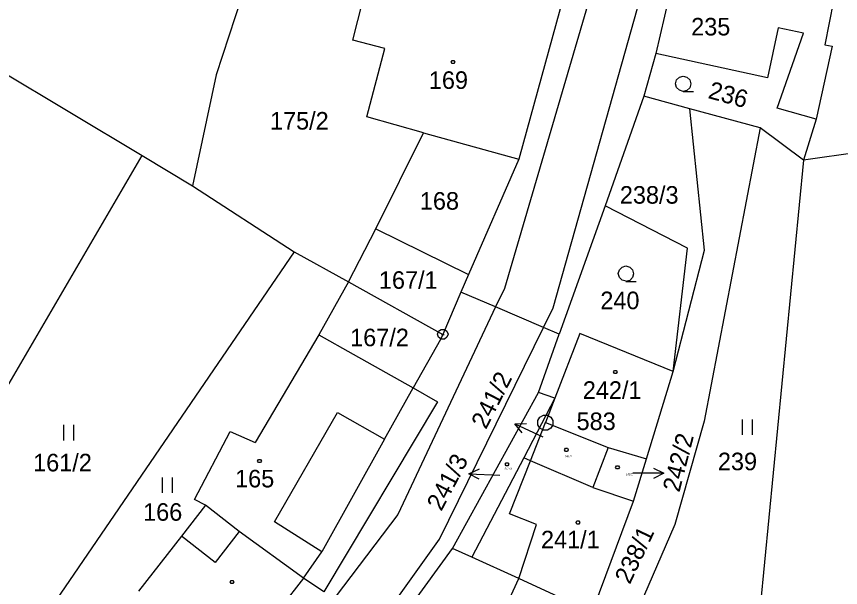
# Model space of a CAD drawing. Extents: x -609861 to -605046, y -1120287 to -1116307.
# Drawn here: x -606958.5 to -606878.7, y -1119189.1 to -1119133.9 of the extents above; entities that cross this region are included whole.
import ezdxf

# ---------------------------------------------------------------- set-up
doc = ezdxf.new("R2010")
doc.units = 0
for name, color, linetype in [('Vrstva 1', 7, 'Continuous'), ('Vrstva 2', 7, 'Continuous'), ('Vrstva 3', 7, 'Continuous'), ('Vrstva 4', 7, 'Continuous'), ('Vrstva 5', 7, 'Continuous'), ('Vrstva 7', 7, 'Continuous'), ('Vrstva 8', 7, 'Continuous')]:
    doc.layers.add(name, color=color, linetype=linetype)

msp = doc.modelspace()

# ---------------------------------------------------------------- linework, layer by layer
at = {"layer": 'Vrstva 1'}
for p, q in [((-606996.59, -1119117.19), (-606946.31, -1119147.33)), ((-606935.08, -1119127.08), (-606939.13, -1119139.5)), ((-606894.56, -1119128.8), (-606896.56, -1119137.46)), ((-606925.9, -1119136.14), (-606924.93, -1119132.36)), ((-606879.35, -1119132.34), (-606880.16, -1119136.62)), ((-606905.8, -1119133.11), (-606909.81, -1119147.66)), ((-606884.68, -1119134.96), (-606885.72, -1119139.79)), ((-606882.23, -1119135.49), (-606884.68, -1119134.96)), ((-606884.78, -1119142.75), (-606882.23, -1119135.49)), ((-606922.81, -1119136.96), (-606925.9, -1119136.14)), ((-606879.46, -1119136.75), (-606881, -1119143.81)), ((-606880.16, -1119136.62), (-606879.46, -1119136.75)), ((-606924.54, -1119143.56), (-606922.81, -1119136.96)), ((-606896.56, -1119137.46), (-606897.7, -1119141.57)), ((-606885.72, -1119139.79), (-606896.56, -1119137.46)), ((-606939.13, -1119139.5), (-606941.43, -1119150.26)), ((-606897.7, -1119141.57), (-606901.47, -1119152.19)), ((-606893.25, -1119142.79), (-606897.7, -1119141.57)), ((-606891.84, -1119156.47), (-606893.25, -1119142.79)), ((-606886.43, -1119144.65), (-606893.25, -1119142.79)), ((-606881, -1119143.81), (-606884.78, -1119142.75)), ((-606919.04, -1119145.12), (-606924.54, -1119143.56)), ((-606851.78, -1119143.47), (-606882.24, -1119147.78)), ((-606881, -1119143.81), (-606882.24, -1119147.78)), ((-606886.43, -1119144.65), (-606891.88, -1119173.02)), ((-606882.24, -1119147.78), (-606886.43, -1119144.65)), ((-606923.67, -1119154.43), (-606919.04, -1119145.12)), ((-606919.04, -1119145.12), (-606909.81, -1119147.66)), ((-606960.14, -1119170.92), (-606946.31, -1119147.33)), ((-606946.31, -1119147.33), (-606941.43, -1119150.26)), ((-606909.81, -1119147.66), (-606914.71, -1119158.84)), ((-606882.24, -1119147.78), (-606887.13, -1119198.08)), ((-606941.43, -1119150.26), (-606931.57, -1119156.63)), ((-606901.47, -1119152.19), (-606905.9, -1119164.62)), ((-606893.48, -1119156.3), (-606901.47, -1119152.19)), ((-606926.33, -1119159.54), (-606923.67, -1119154.43)), ((-606923.67, -1119154.43), (-606914.71, -1119158.84)), ((-606931.57, -1119156.63), (-606960.83, -1119199.39)), ((-606931.57, -1119156.63), (-606926.33, -1119159.54)), ((-606894.87, -1119168.23), (-606893.48, -1119156.3)), ((-606894.87, -1119168.23), (-606891.84, -1119156.47)), ((-606914.71, -1119158.84), (-606915.43, -1119160.54)), ((-606926.33, -1119159.54), (-606929.2, -1119164.69)), ((-606926.33, -1119159.54), (-606917.18, -1119164.63)), ((-606915.43, -1119160.54), (-606917.18, -1119164.63)), ((-606912.07, -1119161.98), (-606915.43, -1119160.54)), ((-606907.43, -1119163.97), (-606912.07, -1119161.98)), ((-606905.9, -1119164.62), (-606907.43, -1119163.97)), ((-606929.2, -1119164.69), (-606935.37, -1119175.1)), ((-606929.2, -1119164.69), (-606925.87, -1119166.55)), ((-606917.18, -1119164.63), (-606917.4, -1119165.14)), ((-606907.92, -1119170.27), (-606905.9, -1119164.62)), ((-606903.9, -1119164.53), (-606906.33, -1119170.8)), ((-606894.87, -1119168.23), (-606903.9, -1119164.53)), ((-606917.4, -1119165.14), (-606920.05, -1119169.81)), ((-606925.87, -1119166.55), (-606920.05, -1119169.81)), ((-606897.46, -1119176.69), (-606894.87, -1119168.23)), ((-606920.05, -1119169.81), (-606917.71, -1119171.16)), ((-606916.25, -1119185.35), (-606907.92, -1119170.27)), ((-606906.33, -1119170.8), (-606907.92, -1119170.27)), ((-606917.71, -1119171.16), (-606928.72, -1119189.54)), ((-606906.33, -1119170.8), (-606909.35, -1119176.58)), ((-606906.33, -1119170.8), (-606907.24, -1119173.17)), ((-606907.24, -1119173.17), (-606901.16, -1119175.59)), ((-606891.88, -1119173.02), (-606894.7, -1119183.02)), ((-606941.23, -1119180.62), (-606937.79, -1119174.02)), ((-606937.79, -1119174.02), (-606935.37, -1119175.1)), ((-606901.16, -1119175.59), (-606902.65, -1119179.44)), ((-606901.16, -1119175.59), (-606897.46, -1119176.69)), ((-606909.35, -1119176.58), (-606914.37, -1119186.2)), ((-606908.69, -1119176.86), (-606909.35, -1119176.58)), ((-606898.71, -1119180.77), (-606897.46, -1119176.69)), ((-606902.65, -1119179.44), (-606908.69, -1119176.86)), ((-606902.65, -1119179.44), (-606898.71, -1119180.77)), ((-606940.18, -1119181.17), (-606941.23, -1119180.62)), ((-606902.71, -1119191.52), (-606898.71, -1119180.77)), ((-606940.18, -1119181.17), (-606942.51, -1119184.16)), ((-606936.9, -1119183.72), (-606940.18, -1119181.17)), ((-606894.7, -1119183.02), (-606899.05, -1119193.07)), ((-606930.67, -1119188.21), (-606936.9, -1119183.72)), ((-606942.51, -1119184.16), (-606946.66, -1119189.47)), ((-606922.12, -1119193.45), (-606916.25, -1119185.35)), ((-606914.37, -1119186.2), (-606916.25, -1119185.35)), ((-606909.82, -1119188.26), (-606914.37, -1119186.2)), ((-606928.72, -1119189.54), (-606930.67, -1119188.21)), ((-606903.65, -1119191.09), (-606909.82, -1119188.26))]:
    msp.add_line(p, q, dxfattribs=at)
at = {"layer": 'Vrstva 3'}
for p, q in [((-606953.94, -1119173.4), (-606953.94, -1119174.9)), ((-606952.94, -1119174.9), (-606952.94, -1119173.4)), ((-606888.18, -1119172.86), (-606888.18, -1119174.36)), ((-606887.18, -1119174.36), (-606887.18, -1119172.86)), ((-606944.38, -1119178.47), (-606944.38, -1119179.97)), ((-606943.38, -1119179.97), (-606943.38, -1119178.47))]:
    msp.add_line(p, q, dxfattribs=at)
for points in [[(-606893.89, -1119141.11), (-606894.27, -1119141.01), (-606894.54, -1119140.74), (-606894.64, -1119140.37), (-606894.54, -1119140), (-606894.27, -1119139.73), (-606893.9, -1119139.63), (-606893.53, -1119139.73), (-606893.26, -1119140), (-606893.16, -1119140.38), (-606893.26, -1119140.76), (-606893.53, -1119141.03), (-606893.91, -1119141.13), (-606892.91, -1119141.13)], [(-606899.43, -1119159.49), (-606899.81, -1119159.39), (-606900.08, -1119159.12), (-606900.18, -1119158.75), (-606900.08, -1119158.38), (-606899.81, -1119158.11), (-606899.44, -1119158.01), (-606899.07, -1119158.11), (-606898.8, -1119158.38), (-606898.7, -1119158.76), (-606898.8, -1119159.14), (-606899.07, -1119159.41), (-606899.45, -1119159.51), (-606898.45, -1119159.51)]]:
    msp.add_lwpolyline(points, dxfattribs=at)
for points in [[(-606900.38, -1119168.11), (-606900.29, -1119168.26), (-606900.38, -1119168.41), (-606900.56, -1119168.41), (-606900.65, -1119168.26), (-606900.56, -1119168.11)], [(-606900.17, -1119177.35), (-606900.08, -1119177.5), (-606900.17, -1119177.65), (-606900.35, -1119177.65), (-606900.44, -1119177.5), (-606900.35, -1119177.35)]]:
    msp.add_lwpolyline(points, close=True, dxfattribs=at)
at = {"layer": 'Vrstva 4'}
for p, q in [((-606900.55, -1119123.83), (-606911.22, -1119160.18)), ((-606906.49, -1119162.06), (-606896.03, -1119124.84)), ((-606911.22, -1119160.18), (-606912.07, -1119161.98)), ((-606912.07, -1119161.98), (-606921.54, -1119182.07)), ((-606907.43, -1119163.97), (-606906.49, -1119162.06)), ((-606917.5, -1119184.46), (-606907.43, -1119163.97)), ((-606922.82, -1119174.77), (-606920.05, -1119169.81)), ((-606933.49, -1119182.77), (-606927.37, -1119172.19)), ((-606927.37, -1119172.19), (-606922.82, -1119174.77)), ((-606908.69, -1119176.86), (-606907.24, -1119173.17)), ((-606922.82, -1119174.77), (-606928.91, -1119185.68)), ((-606910.72, -1119182), (-606908.69, -1119176.86)), ((-606921.54, -1119182.07), (-606931.69, -1119195.44)), ((-606908.12, -1119183.03), (-606910.72, -1119182)), ((-606928.91, -1119185.68), (-606933.49, -1119182.77)), ((-606909.82, -1119188.26), (-606908.12, -1119183.03)), ((-606936.9, -1119183.72), (-606939.24, -1119186.72)), ((-606939.24, -1119186.72), (-606942.51, -1119184.16)), ((-606927.84, -1119198.87), (-606917.5, -1119184.46)), ((-606930.67, -1119188.21), (-606928.91, -1119185.68)), ((-606930.67, -1119188.21), (-606937.17, -1119196.54)), ((-606912.14, -1119193.29), (-606909.82, -1119188.26))]:
    msp.add_line(p, q, dxfattribs=at)
at = {"layer": 'Vrstva 5'}
for points in [[(-606916.11, -1119138.12), (-606916.02, -1119138.27), (-606916.11, -1119138.42), (-606916.29, -1119138.42), (-606916.38, -1119138.27), (-606916.29, -1119138.12)], [(-606905.12, -1119175.65), (-606905.03, -1119175.8), (-606905.12, -1119175.95), (-606905.3, -1119175.95), (-606905.39, -1119175.8), (-606905.3, -1119175.65)], [(-606934.85, -1119176.74), (-606934.76, -1119176.89), (-606934.85, -1119177.04), (-606935.03, -1119177.04), (-606935.12, -1119176.89), (-606935.03, -1119176.74)], [(-606910.88, -1119177.05), (-606910.79, -1119177.2), (-606910.88, -1119177.35), (-606911.06, -1119177.35), (-606911.15, -1119177.2), (-606911.06, -1119177.05)], [(-606904.01, -1119182.69), (-606903.92, -1119182.84), (-606904.01, -1119182.99), (-606904.19, -1119182.99), (-606904.28, -1119182.84), (-606904.19, -1119182.69)], [(-606937.51, -1119188.44), (-606937.42, -1119188.59), (-606937.51, -1119188.74), (-606937.69, -1119188.74), (-606937.78, -1119188.59), (-606937.69, -1119188.44)]]:
    msp.add_lwpolyline(points, close=True, dxfattribs=at)
at = {"layer": 'Vrstva 7'}
for p, q in [((-606910.202, -1119173.299), (-606907.48, -1119174.56)), ((-606914.647, -1119178.115), (-606911.65, -1119178.24)), ((-606895.77, -1119178.071), (-606898.77, -1119178.07))]:
    msp.add_line(p, q, dxfattribs=at)
for points in [[(-606909.505, -1119174.173), (-606910.202, -1119173.299), (-606909.085, -1119173.266)], [(-606896.77, -1119177.571), (-606895.77, -1119178.071), (-606896.77, -1119178.571)], [(-606913.669, -1119178.656), (-606914.647, -1119178.115), (-606913.627, -1119177.657)]]:
    msp.add_lwpolyline(points, dxfattribs=at)
at = {"layer": 'Vrstva 8'}
for p, q in [((-606917.3, -1119164.63), (-606917.06, -1119164.63)), ((-606907.29, -1119173.17), (-606907.19, -1119173.17))]:
    msp.add_line(p, q, dxfattribs=at)
for points in [[(-606917.03, -1119164.15), (-606916.78, -1119164.33), (-606916.68, -1119164.62), (-606916.78, -1119164.91), (-606917.03, -1119165.09), (-606917.34, -1119165.09), (-606917.59, -1119164.91), (-606917.69, -1119164.62), (-606917.59, -1119164.33), (-606917.34, -1119164.15)], [(-606907.05, -1119172.45), (-606906.71, -1119172.64), (-606906.52, -1119172.98), (-606906.52, -1119173.37), (-606906.71, -1119173.71), (-606907.05, -1119173.9), (-606907.44, -1119173.9), (-606907.78, -1119173.71), (-606907.97, -1119173.37), (-606907.97, -1119172.98), (-606907.78, -1119172.64), (-606907.44, -1119172.45)]]:
    msp.add_lwpolyline(points, close=True, dxfattribs=at)

# ---------------------------------------------------------------- texts
at = {"layer": 'Vrstva 2'}
for s, height, p in [('235', 1.7, (-606893.123, -1119135.7)), ('169', 1.7, (-606918.537, -1119140.87)), ('175/2', 1.7, (-606933.927, -1119144.81)), ('238/3', 1.7, (-606900.033, -1119151.98)), ('168', 1.7, (-606919.407, -1119152.56)), ('167/1', 1.7, (-606923.377, -1119160.22)), ('240', 1.7, (-606901.923, -1119162.19)), ('167/2', 1.7, (-606926.159, -1119165.78)), ('242/1', 1.7, (-606903.623, -1119170.87)), ('161/2', 1.7, (-606956.871, -1119177.89)), ('241/2', 0.2, (-606905.362, -1119176.54)), ('239', 1.7, (-606890.533, -1119177.78)), ('241/3', 0.2, (-606911.192, -1119177.73)), ('165', 1.7, (-606937.307, -1119179.44)), ('242/2', 0.2, (-606899.462, -1119178.26)), ('166', 1.7, (-606946.217, -1119182.67)), ('241/1', 1.7, (-606907.673, -1119185.34))]:
    msp.add_text(s, height=height, dxfattribs=at).set_placement(p)
for s, rotation, p in [('236', 344.69141, (-606891.571, -1119141.743)), ('238/1', 64.80153, (-606899.069, -1119188.895))]:
    msp.add_text(s, height=1.7, rotation=rotation, dxfattribs=at).set_placement(p)
at = {"layer": 'Vrstva 7'}
for s, rotation, p in [('241/2', 63.02536, (-606913, -1119173.894)), ('242/2', 75.57313, (-606894.268, -1119179.982)), ('241/3', 62.10862, (-606917.327, -1119181.816))]:
    msp.add_text(s, height=1.7, rotation=rotation, dxfattribs=at).set_placement(p)
at = {"layer": 'Vrstva 8'}
msp.add_text('583', height=1.7, dxfattribs=at).set_placement((-606904.223, -1119173.89))

doc.saveas('drawing.dxf')
